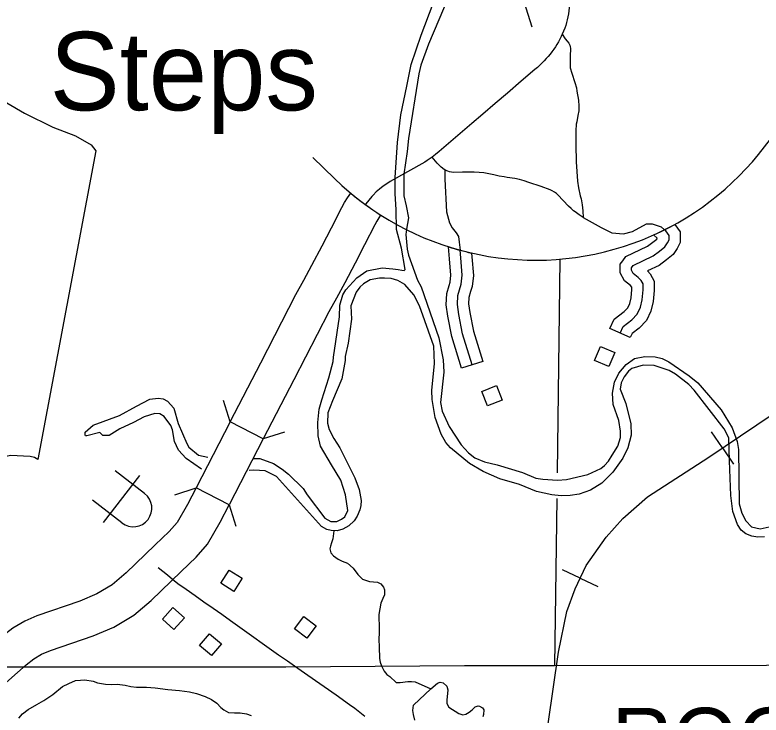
# Model space of a CAD drawing. Extents: x -19 to 366, y -4 to 359.
# Drawn here: x 142.697 to 143.649, y 197.976 to 198.869 of the extents above; entities that cross this region are included whole.
import ezdxf

# ---------------------------------------------------------------- set-up
doc = ezdxf.new("R2010")
doc.units = 0
for name, color, linetype in [('Level 10', 7, 'Continuous'), ('Level 24', 7, 'Continuous'), ('Level 31', 7, 'Continuous'), ('Level 32', 7, 'Continuous'), ('Level 35', 7, 'Continuous'), ('Level 37', 7, 'Continuous'), ('Level 40', 7, 'Continuous'), ('Level 5', 7, 'Continuous'), ('Level 50', 7, 'Continuous'), ('Level 56', 7, 'Continuous'), ('Level 57', 7, 'Continuous'), ('Level 60', 7, 'Continuous'), ('Level 63', 7, 'Continuous'), ('Level 9', 7, 'Continuous')]:
    doc.layers.add(name, color=color, linetype=linetype)

msp = doc.modelspace()

# ---------------------------------------------------------------- linework, layer by layer
at = {"layer": 'Level 10'}
for p, q in [((143.01371, 198.32807), (142.97164, 198.34979)), ((142.97012, 198.24366), (142.92805, 198.26538)), ((142.86331, 198.1804), (142.8633, 198.1804))]:
    msp.add_line(p, q, dxfattribs=at)
for points in [[(143.40417, 198.88423), (143.40409, 198.88139), (143.40383, 198.87758), (143.40345, 198.87378), (143.40292, 198.87), (143.40225, 198.86624), (143.40144, 198.86251), (143.40049, 198.85881), (143.39939, 198.85516), (143.39817, 198.85154), (143.39681, 198.84797), (143.39508, 198.84394)], [(143.39508, 198.84394), (143.39375, 198.84103), (143.39205, 198.83764), (143.39023, 198.83432), (143.38832, 198.83105), (143.38628, 198.82785), (143.38417, 198.82472), (143.38194, 198.82165), (143.37959, 198.81867), (143.37717, 198.81576), (143.37465, 198.81293), (143.37203, 198.81019), (143.36934, 198.80753), (143.36334, 198.8016), (143.36022, 198.79879), (143.34283, 198.78409), (143.32507, 198.76896), (143.30965, 198.75576), (143.29388, 198.74222), (143.27967, 198.73011), (143.23825, 198.69453), (143.23331, 198.69039), (143.22935, 198.68738)], [(143.22935, 198.68738), (143.22288, 198.68282), (143.2196, 198.68074), (143.17569, 198.65616), (143.17116, 198.65329), (143.16652, 198.65004), (143.16206, 198.64654), (143.15779, 198.64281), (143.15371, 198.63886), (143.15211, 198.63707), (143.1482, 198.63243), (143.14455, 198.62761), (143.14395, 198.62673)], [(142.97164, 198.34979), (143.01053, 198.42512), (143.0555, 198.51224), (143.06561, 198.53029), (143.0759, 198.54936), (143.08903, 198.57406), (143.1007, 198.59702), (143.11417, 198.62321), (143.11749, 198.6293), (143.12126, 198.63546), (143.12526, 198.64135)], [(143.16347, 198.61333), (143.16104, 198.60977), (143.15849, 198.6056), (143.15602, 198.60106), (143.14286, 198.57547), (143.13104, 198.55222), (143.11763, 198.52701), (143.1071, 198.50748), (143.0972, 198.48981), (143.0526, 198.4034), (143.01371, 198.32807)], [(142.97164, 198.34979), (142.92805, 198.26538)], [(143.01371, 198.32807), (142.97012, 198.24366)], [(142.92805, 198.26538), (142.91718, 198.24432), (142.9039, 198.22135), (142.89392, 198.20998), (142.87607, 198.19272), (142.86331, 198.1804)], [(142.89619, 198.14633), (142.90897, 198.15867), (142.92822, 198.17729), (142.94256, 198.19362), (142.95873, 198.22159), (142.97012, 198.24366)], [(142.8633, 198.1804), (142.8391, 198.15703), (142.82098, 198.14198), (142.80157, 198.13019), (142.77981, 198.12101), (142.72522, 198.10222), (142.70968, 198.09557), (142.69453, 198.0866), (142.68137, 198.07628), (142.52507, 197.93861), (142.4898, 197.90757), (142.47396, 197.8914), (142.46067, 197.87294), (142.43613, 197.83227), (142.43194, 197.82633)], [(142.47062, 197.79903), (142.47579, 197.80635), (142.50021, 197.84683), (142.51029, 197.86082), (142.5224, 197.87318), (142.55636, 197.90308), (142.71165, 198.03986), (142.72131, 198.04743), (142.73114, 198.05325), (142.74227, 198.05801), (142.79673, 198.07676), (142.82319, 198.08792), (142.84854, 198.10333), (142.87071, 198.12174), (142.89619, 198.14634)]]:
    msp.add_lwpolyline(points, dxfattribs=at)
msp.add_arc((143.36999, 198.93506), 0.3823, 230.19832, 237.30333, dxfattribs=at)
at = {"layer": 'Level 31'}
for p, q in [((143.47228, 198.5552), (143.47228, 198.5552)), ((143.25094, 198.52364), (143.25094, 198.52364)), ((143.48169, 198.45707), (143.45582, 198.46882)), ((143.29358, 198.42654), (143.2664, 198.41831))]:
    msp.add_line(p, q, dxfattribs=at)
for points in [[(143.39508, 198.84394), (143.39857, 198.83816), (143.40122, 198.83503), (143.40322, 198.83253), (143.40457, 198.83), (143.40529, 198.8281), (143.40559, 198.82609), (143.40546, 198.82406), (143.4052, 198.81759), (143.40506, 198.80117), (143.40706, 198.79429), (143.41113, 198.78262), (143.41338, 198.77576), (143.41377, 198.77141), (143.41554, 198.75982), (143.41614, 198.7524), (143.41606, 198.74638), (143.41508, 198.74032), (143.41355, 198.7322), (143.41259, 198.72931), (143.4122, 198.72097), (143.41225, 198.70277), (143.41264, 198.68119), (143.41454, 198.6565), (143.41581, 198.64808), (143.41804, 198.63776), (143.41917, 198.63405), (143.42029, 198.62652), (143.42131, 198.61861), (143.42168, 198.61016)], [(143.42168, 198.61016), (143.41678, 198.61347), (143.41133, 198.61746), (143.40953, 198.61887), (143.40627, 198.62171), (143.4032, 198.62475), (143.38952, 198.6393), (143.38751, 198.641), (143.38497, 198.64276), (143.38229, 198.64426), (143.37946, 198.6455), (143.36796, 198.64977), (143.35236, 198.65504), (143.3465, 198.65695), (143.34063, 198.65856), (143.33467, 198.65988), (143.3248, 198.66137), (143.32113, 198.66191), (143.31439, 198.66315), (143.30771, 198.66467), (143.29737, 198.66685), (143.29511, 198.66717), (143.289, 198.66781), (143.28288, 198.66814), (143.27675, 198.66818), (143.27267, 198.6682), (143.26782, 198.6681), (143.25632, 198.66782), (143.2538, 198.66798), (143.25135, 198.66845), (143.24896, 198.6692), (143.24668, 198.67024), (143.24453, 198.67154), (143.2408, 198.67445), (143.23812, 198.67693), (143.23564, 198.67961), (143.22935, 198.68738)], [(143.24536, 198.67104), (143.24516, 198.65914), (143.24757, 198.61768), (143.25117, 198.60326), (143.25477, 198.59725), (143.25957, 198.59065), (143.26258, 198.58584), (143.26378, 198.57863), (143.26469, 198.56861)], [(143.42168, 198.61016), (143.44472, 198.59767), (143.45845, 198.5908), (143.47295, 198.58928), (143.48477, 198.59233), (143.50232, 198.60225), (143.50957, 198.60225), (143.52101, 198.59844), (143.52538, 198.59461)], [(143.53854, 198.60153), (143.54551, 198.59202), (143.54551, 198.57829), (143.54166, 198.57057), (143.53641, 198.56299), (143.52777, 198.55627), (143.51854, 198.54923), (143.50358, 198.54208)], [(143.46875, 198.46295), (143.47257, 198.47134), (143.48363, 198.47974), (143.4905, 198.48699), (143.49469, 198.49577), (143.49698, 198.50531), (143.49812, 198.51791), (143.49812, 198.52554), (143.49584, 198.52974), (143.49164, 198.53394), (143.48554, 198.5389), (143.48325, 198.5431), (143.48325, 198.54615), (143.48554, 198.5492), (143.51109, 198.56141), (143.5191, 198.56752), (143.52597, 198.57286), (143.5294, 198.57783), (143.53131, 198.58164), (143.53131, 198.58737), (143.52711, 198.59309), (143.52538, 198.59461)], [(143.47228, 198.5552), (143.47626, 198.56051), (143.50365, 198.5736), (143.51044, 198.57877), (143.51553, 198.58274), (143.51623, 198.58375), (143.5114, 198.58797)], [(143.25094, 198.52364), (143.25219, 198.52791), (143.25312, 198.53675), (143.25143, 198.55759), (143.25003, 198.57291)], [(143.27999, 198.42243), (143.26798, 198.46208), (143.26318, 198.48671), (143.26138, 198.49933), (143.26198, 198.51074), (143.26618, 198.52516), (143.26738, 198.53658), (143.26558, 198.5588), (143.26469, 198.56861)], [(143.27928, 198.56496), (143.27973, 198.56002), (143.28165, 198.5364), (143.28017, 198.52241), (143.27822, 198.51569)], [(143.45582, 198.46882), (143.46112, 198.48049), (143.47411, 198.49035), (143.47864, 198.49514), (143.48123, 198.50054), (143.48293, 198.50762), (143.48392, 198.51855), (143.48392, 198.52157), (143.48211, 198.52338), (143.4744, 198.52964), (143.46904, 198.53948), (143.46904, 198.55088), (143.47228, 198.5552)], [(143.50358, 198.54208), (143.50733, 198.53833), (143.51233, 198.52916), (143.51233, 198.51726), (143.51103, 198.503), (143.50815, 198.491), (143.50235, 198.47885), (143.49314, 198.46913), (143.48402, 198.4622), (143.48169, 198.45707)], [(143.2664, 198.41831), (143.25418, 198.45865), (143.24917, 198.48435), (143.24712, 198.49869), (143.24788, 198.51313), (143.25094, 198.52364)], [(143.27822, 198.51569), (143.27607, 198.50835), (143.27563, 198.49996), (143.27719, 198.48907), (143.28178, 198.4655), (143.29358, 198.42654)], [(143.14343, 197.97369), (143.13709, 197.97901), (143.13059, 197.98409), (143.12386, 197.98894), (143.10685, 198.00097), (143.07044, 198.02632), (143.06616, 198.02929), (143.05796, 198.03491), (143.05346, 198.03803), (143.04456, 198.0443), (143.03341, 198.05217), (143.02147, 198.06066), (142.99274, 198.08121), (142.97203, 198.0959), (142.96085, 198.10382), (142.94991, 198.11155), (142.93806, 198.11984), (142.92698, 198.12759), (142.91544, 198.13574), (142.90505, 198.1432), (142.89795, 198.14876), (142.8918, 198.15402), (142.87975, 198.16337)]]:
    msp.add_lwpolyline(points, dxfattribs=at)
for centre, radius, start, end in [((143.36097, 198.92315), 0.36738, 294.17111, 298.90429), ((143.36097, 198.92313), 0.36737, 252.42411, 257.15276)]:
    msp.add_arc(centre, radius, start, end, dxfattribs=at)
at = {"layer": 'Level 32'}
msp.add_lwpolyline([(143.33736, 198.9305), (143.33703, 198.91934), (143.33823, 198.91033), (143.35624, 198.85325)], dxfattribs=at)
at = {"layer": 'Level 35'}
for points in [[(142.80029, 198.69527), (142.72628, 198.30157)], [(143.10377, 198.21087), (143.10243, 198.20043), (143.1009, 198.19531), (143.09938, 198.19133), (143.09862, 198.18772), (143.09994, 198.18241), (143.10335, 198.17861), (143.10921, 198.17443), (143.11451, 198.17215), (143.12114, 198.1693), (143.12852, 198.16322), (143.13457, 198.15487), (143.14044, 198.14917), (143.14915, 198.14613), (143.15937, 198.14536), (143.16373, 198.14327), (143.16713, 198.1389), (143.16827, 198.13549), (143.16826, 198.12885), (143.16617, 198.12448), (143.1637, 198.11842), (143.16122, 198.10381), (143.16138, 198.08522), (143.16138, 198.08085), (143.16118, 198.07212), (143.16136, 198.06264), (143.16191, 198.04784), (143.16304, 198.04328), (143.16455, 198.03854), (143.16795, 198.03152), (143.17135, 198.02753), (143.17533, 198.02506), (143.18308, 198.01746), (143.1882, 198.01708), (143.19805, 198.0184), (143.20297, 198.01858), (143.20733, 198.01801), (143.2274, 198.00908)], [(143.2274, 198.00908), (143.23593, 198.01628), (143.23953, 198.0176), (143.24313, 198.01684), (143.24805, 198.01266), (143.24899, 198.00773), (143.24803, 197.99483), (143.24765, 197.99274), (143.24783, 197.99028), (143.25029, 197.98572), (143.26316, 197.97755), (143.26808, 197.97622), (143.27187, 197.97678), (143.27642, 197.97925), (143.28002, 197.98228), (143.28401, 197.98626), (143.28647, 197.9872), (143.2878, 197.98758), (143.2895, 197.9872), (143.29348, 197.98511), (143.29499, 197.98245), (143.29479, 197.97638), (143.29365, 197.97335)], [(143.20708, 197.96925), (143.20538, 197.97627), (143.20444, 197.98159), (143.2054, 197.98842), (143.2274, 198.00908)]]:
    msp.add_lwpolyline(points, dxfattribs=at)
at = {"layer": 'Level 37'}
for points in [[(142.97164, 198.34979), (142.963, 198.37685)], [(143.04077, 198.3367), (143.01371, 198.32807)], [(142.90099, 198.25674), (142.92805, 198.26538)], [(142.97012, 198.24366), (142.97876, 198.21659)]]:
    msp.add_lwpolyline(points, dxfattribs=at)
at = {"layer": 'Level 40'}
for p, q in [((143.59933, 198.31636), (143.58536, 198.33709)), ((143.59933, 198.31636), (143.6133, 198.29563)), ((143.41788, 198.1503), (143.3953, 198.16105)), ((143.41788, 198.1503), (143.44045, 198.13956))]:
    msp.add_line(p, q, dxfattribs=at)
for points in [[(143.45095, 198.20245), (143.47209, 198.22643), (143.5038, 198.25392), (143.58202, 198.30469), (143.68349, 198.37308), (143.72084, 198.40128), (143.7455, 198.42455), (143.76734, 198.45063), (143.78778, 198.48377), (143.80399, 198.52184), (143.81597, 198.57049), (143.81949, 198.60434), (143.81597, 198.64311), (143.80892, 198.67978), (143.79342, 198.71997), (143.6849, 198.93219), (143.49394, 199.29811), (143.30931, 199.65769), (143.18177, 199.90658), (143.1564, 199.93901), (143.12821, 199.9651), (143.10496, 199.98343)], [(143.37062, 197.92043), (143.39035, 198.0558), (143.40092, 198.10798), (143.41149, 198.13688), (143.42558, 198.1665), (143.45095, 198.20245), (143.47209, 198.22643), (143.5038, 198.25392), (143.58202, 198.30469), (143.68349, 198.37308)], [(143.37062, 197.92043), (143.39035, 198.0558), (143.40092, 198.10798), (143.41149, 198.13688), (143.42558, 198.1665), (143.45095, 198.20245)]]:
    msp.add_lwpolyline(points, dxfattribs=at)
at = {"layer": 'Level 5'}
for points in [[(143.39211, 198.55709), (143.38851, 198.28475)], [(143.38807, 198.25188), (143.38526, 198.03905)]]:
    msp.add_lwpolyline(points, dxfattribs=at)
at = {"layer": 'Level 50'}
msp.add_lwpolyline([(142.70203, 197.97177), (142.70673, 197.9773), (142.7139, 197.98304), (142.72522, 197.989), (142.73389, 197.99419), (142.74559, 198.00205), (142.75765, 198.01219), (142.76576, 198.01604), (142.77425, 198.0197), (142.78068, 198.02031), (142.78616, 198.02054), (142.79695, 198.01909), (142.80244, 198.01704), (142.81266, 198.01502), (142.82004, 198.01469), (142.8276, 198.01512), (142.83782, 198.01386), (142.84501, 198.0122), (142.8522, 198.01111), (142.85939, 198.01116), (142.86506, 198.01139), (142.87584, 198.01051), (142.8923, 198.00834), (142.90687, 198.00692), (142.91954, 198.0053), (142.92844, 198.00327), (142.9398, 197.99955), (142.94795, 197.99562), (142.9544, 197.99111), (142.95952, 197.98545), (142.96332, 197.98225), (142.96939, 197.97887), (142.97695, 197.97855), (142.98433, 197.97841), (142.99227, 197.97713), (142.99814, 197.97527)], dxfattribs=at)
at = {"layer": 'Level 56'}
for points in [[(143.46192, 198.43822), (143.45422, 198.42008), (143.43602, 198.4278), (143.44372, 198.44595)], [(143.311, 198.39582), (143.31825, 198.37749), (143.29986, 198.37022), (143.29261, 198.38855)], [(142.98693, 198.15013), (142.9764, 198.13346), (142.95968, 198.14402), (142.97021, 198.16069)], [(142.91315, 198.09959), (142.89993, 198.08497), (142.88526, 198.09822), (142.89848, 198.11285)], [(143.08113, 198.08949), (143.06927, 198.07374), (143.05347, 198.08563), (143.06533, 198.10138)], [(142.94529, 198.07938), (142.96037, 198.06667), (142.94763, 198.05155), (142.93255, 198.06426)]]:
    msp.add_lwpolyline(points, close=True, dxfattribs=at)
at = {"layer": 'Level 57'}
for p, q in [((142.86255, 198.2583), (142.82507, 198.28725)), ((142.80993, 198.22117), (142.85624, 198.28112)), ((142.8336, 198.22083), (142.79613, 198.24977))]:
    msp.add_line(p, q, dxfattribs=at)
msp.add_arc((142.84807, 198.23957), 0.02367, 232.31688, 52.31688, dxfattribs=at)
at = {"layer": 'Level 60'}
for points in [[(146.77834, 1.69699), (146.57878, 10.31313), (146.37852, 18.92942), (146.17757, 27.54584), (145.97591, 36.16241), (145.77356, 44.77911), (145.57052, 53.39596), (145.36679, 62.01295), (145.16236, 70.63008), (144.95724, 79.24735), (144.75142, 87.86477), (144.54492, 96.48232), (144.33773, 105.10002), (144.12986, 113.71787), (143.92129, 122.33585), (143.71204, 130.95398), (143.5021, 139.57225), (143.29148, 148.19067), (143.08018, 156.80923), (142.8682, 165.42794), (142.65553, 174.04679), (142.44218, 182.66579), (142.22816, 191.28493), (142.01345, 199.90421), (141.79807, 208.52365), (141.58202, 217.14322), (141.36528, 225.76295), (141.14788, 234.38282), (140.9298, 243.00284), (140.71105, 251.623), (140.49162, 260.24332), (140.27153, 268.86377), (140.05077, 277.48438), (139.82934, 286.10514), (139.60724, 294.72604), (139.38447, 303.34709), (139.16105, 311.96829), (138.93695, 320.58964), (138.7122, 329.21114), (138.48678, 337.83278), (138.2607, 346.45458)], [(0, 198.13258), (7.10141, 198.13701), (14.2028, 198.15029), (21.30418, 198.17244), (28.40552, 198.20345), (35.50682, 198.24331), (42.60806, 198.29203), (49.70923, 198.34961), (56.81033, 198.41605), (63.91134, 198.49135), (71.01225, 198.5755), (78.11305, 198.66852), (85.21373, 198.77039), (92.31428, 198.88112), (99.41468, 199.0007), (106.51492, 199.12915), (113.61501, 199.26645), (120.71491, 199.4126), (127.81463, 199.56762), (134.91415, 199.73149), (142.01345, 199.90421), (149.11254, 200.0858), (156.2114, 200.27623), (163.31001, 200.47553), (170.40837, 200.68367), (177.50646, 200.90068), (184.60427, 201.12653), (191.7018, 201.36125), (198.79903, 201.60481), (205.89596, 201.85723), (212.99256, 202.1185), (220.08883, 202.38862), (227.18475, 202.6676), (234.28033, 202.95542), (241.37554, 203.2521), (248.47037, 203.55763), (255.56482, 203.87201), (262.65887, 204.19524), (269.75251, 204.52732), (276.84573, 204.86824), (283.93852, 205.21802), (291.03086, 205.57664), (298.12276, 205.94411), (305.21419, 206.32042), (312.30515, 206.70559), (319.39562, 207.09959), (326.48559, 207.50244), (333.57505, 207.91414), (340.664, 208.33468)], [(0, 189.51617), (7.11214, 189.52059), (14.22427, 189.53386), (21.33637, 189.55597), (28.44845, 189.58693), (35.56048, 189.62672), (42.67245, 189.67537), (49.78436, 189.73285), (56.89619, 189.79918), (64.00793, 189.87436), (71.11958, 189.95838), (78.23111, 190.05124), (85.34253, 190.15294), (92.45381, 190.26349), (99.56495, 190.38288), (106.67593, 190.51112), (113.78675, 190.6482), (120.89739, 190.79412), (128.00785, 190.94888), (135.11811, 191.11248), (142.22816, 191.28493), (149.33799, 191.46621), (156.44759, 191.65634), (163.55694, 191.85531), (170.66605, 192.06312), (177.77489, 192.27977), (184.88345, 192.50526), (191.99173, 192.73959), (199.09971, 192.98276), (206.20739, 193.23477), (213.31474, 193.49561), (220.42177, 193.7653), (227.52845, 194.04382), (234.63479, 194.33118), (241.74076, 194.62738), (248.84635, 194.93241), (255.95157, 195.24628), (263.05638, 195.56898), (270.16079, 195.90052), (277.26478, 196.24089), (284.36834, 196.5901), (291.47147, 196.94814), (298.57414, 197.31501), (305.67635, 197.69072), (312.77809, 198.07525), (319.87934, 198.46862), (326.9801, 198.87082), (334.08035, 199.28185), (341.18009, 199.7017)]]:
    msp.add_spline(points, degree=3, dxfattribs=at)
at = {"layer": 'Level 63'}
for points in [[(143.07701, 198.68687), (143.10468, 198.65993)], [(140.83205, 198.03809), (141.26817, 198.0367), (141.39108, 198.03674), (142.26862, 198.03703), (142.39046, 198.03707), (143.04238, 198.03729), (143.27017, 198.03888), (143.38526, 198.03905), (145.27639, 198.04185)]]:
    msp.add_lwpolyline(points, dxfattribs=at)
msp.add_arc((143.36097, 198.92314), 0.36738, 225.76353, 349.85724, dxfattribs=at)
at = {"layer": 'Level 9'}
for points in [[(142.20175, 198.96157), (142.23718, 198.9499), (142.25951, 198.93938), (142.29895, 198.91257), (142.31347, 198.90479), (142.32834, 198.89872), (142.34906, 198.89539), (142.37079, 198.88714), (142.39021, 198.88133), (142.41131, 198.87743), (142.42534, 198.87743), (142.44187, 198.87461), (142.47175, 198.86685), (142.52482, 198.84117), (142.56668, 198.81743), (142.6413, 198.78293), (142.70936, 198.74341), (142.74545, 198.72547), (142.77423, 198.71447), (142.79449, 198.70278), (142.80029, 198.69527)], [(143.25095, 198.89391), (143.22454, 198.8313), (143.21469, 198.8046), (143.212, 198.79356)], [(143.185, 198.70589), (143.18905, 198.74124), (143.19706, 198.7776), (143.20217, 198.80519), (143.21528, 198.84295), (143.23044, 198.8832)], [(143.212, 198.79356), (143.19896, 198.7112), (143.1973, 198.69447), (143.19316, 198.66557), (143.19317, 198.63804), (143.19583, 198.62498), (143.19908, 198.60965), (143.19625, 198.59538), (143.19577, 198.58873), (143.19718, 198.56977), (143.1988, 198.56239), (143.21045, 198.53027), (143.21512, 198.52199), (143.23747, 198.45661), (143.24337, 198.4286), (143.24397, 198.41304), (143.23979, 198.37427), (143.24184, 198.36328), (143.25065, 198.34385), (143.26596, 198.32033), (143.27539, 198.3102), (143.28364, 198.30386), (143.29603, 198.29871), (143.31183, 198.29475), (143.3442, 198.28493), (143.36117, 198.27794), (143.3701, 198.27654), (143.38907, 198.27546), (143.40025, 198.27618), (143.42784, 198.28262), (143.44404, 198.29005), (143.44891, 198.29391), (143.45395, 198.29967), (143.45877, 198.30714), (143.466, 198.31881), (143.46944, 198.32987), (143.46933, 198.33784), (143.46705, 198.35147), (143.45975, 198.37169), (143.45897, 198.3861), (143.46161, 198.40037)], [(143.17896, 198.54479), (143.18579, 198.54411), (143.19055, 198.54311), (143.19359, 198.54277), (143.19452, 198.54392), (143.18996, 198.57119), (143.18355, 198.59483), (143.18338, 198.62064), (143.18195, 198.64055), (143.18203, 198.66143), (143.185, 198.70589)], [(143.10328, 198.43211), (143.11093, 198.48343), (143.11147, 198.49862), (143.11508, 198.51157), (143.11897, 198.51808), (143.13316, 198.53345), (143.14573, 198.54235), (143.16559, 198.54603), (143.17896, 198.54479)], [(143.16845, 198.533), (143.16179, 198.53307), (143.15007, 198.53064), (143.14161, 198.52578), (143.13693, 198.52155), (143.13228, 198.51522), (143.12533, 198.49748), (143.12614, 198.48078), (143.12189, 198.44988), (143.11842, 198.43291)], [(143.60747, 198.32924), (143.60162, 198.34055), (143.56338, 198.38996), (143.55626, 198.39745), (143.53939, 198.41033), (143.53136, 198.41534), (143.51212, 198.42173), (143.49828, 198.42174), (143.48355, 198.41756), (143.47961, 198.41447), (143.47403, 198.40718), (143.46997, 198.39953), (143.46895, 198.39117), (143.47622, 198.37304), (143.48266, 198.34713), (143.48305, 198.33271), (143.47855, 198.31632), (143.4721, 198.30333), (143.45965, 198.28532), (143.44544, 198.27128), (143.43097, 198.26235), (143.41663, 198.25742), (143.40528, 198.25575), (143.39372, 198.25541), (143.38157, 198.25638), (143.36217, 198.26087), (143.34062, 198.26988), (143.3153, 198.27695), (143.29413, 198.28635), (143.27672, 198.29675), (143.25255, 198.31654), (143.24677, 198.32349), (143.24055, 198.33404), (143.23304, 198.35519), (143.2293, 198.3783), (143.22857, 198.38968), (143.23225, 198.42389), (143.23136, 198.44628), (143.21281, 198.49747), (143.20579, 198.51161), (143.19441, 198.52475), (143.18518, 198.53003), (143.17692, 198.5325), (143.16845, 198.533)], [(143.00182, 198.30312), (143.00932, 198.30287), (143.02704, 198.29646), (143.03795, 198.28939), (143.046, 198.28286), (143.06447, 198.2645), (143.06969, 198.25679), (143.09231, 198.22672), (143.09976, 198.22246), (143.10753, 198.22256), (143.11375, 198.22549), (143.11787, 198.22858), (143.12155, 198.23679), (143.1188, 198.25649), (143.11266, 198.2752), (143.10081, 198.29498), (143.08663, 198.3187), (143.08398, 198.33195), (143.08317, 198.34865), (143.0852, 198.36595), (143.08825, 198.37794), (143.09733, 198.40578), (143.10291, 198.42673), (143.10328, 198.43211)], [(143.11842, 198.43291), (143.11826, 198.42769), (143.11385, 198.40448), (143.10211, 198.37642), (143.09626, 198.36135), (143.09589, 198.34787)], [(143.46161, 198.40037), (143.46714, 198.41164), (143.47665, 198.42278), (143.48734, 198.43051), (143.50039, 198.43315), (143.51348, 198.43276), (143.52223, 198.43041), (143.53101, 198.42616), (143.55705, 198.40828), (143.56798, 198.39951), (143.59786, 198.36517), (143.61165, 198.3422), (143.61797, 198.32444), (143.61982, 198.31422), (143.62081, 198.24495), (143.62401, 198.23303), (143.62927, 198.22323), (143.63639, 198.21593), (143.64723, 198.21341), (143.65876, 198.21585)], [(142.93518, 198.28918), (142.91566, 198.30276), (142.90584, 198.31364), (142.90075, 198.32477), (142.89789, 198.33935), (142.89591, 198.34502), (142.88722, 198.35629), (142.88186, 198.35982), (142.87541, 198.36031), (142.86181, 198.35614), (142.84846, 198.34875), (142.83075, 198.34092), (142.81741, 198.3322), (142.80907, 198.33228), (142.80541, 198.33603), (142.78879, 198.33182), (142.78727, 198.33199), (142.78649, 198.33331), (142.78664, 198.33654), (142.79694, 198.34522), (142.83032, 198.35762), (142.85195, 198.36968), (142.86927, 198.37845), (142.87968, 198.37973), (142.88614, 198.37886), (142.89187, 198.3759), (142.89957, 198.36727), (142.90516, 198.34761), (142.91614, 198.32213), (142.91905, 198.31742), (142.93115, 198.30714)], [(143.09589, 198.34787), (143.09789, 198.34011), (143.10394, 198.32823), (143.11131, 198.31637), (143.13063, 198.2781), (143.13615, 198.26318), (143.13843, 198.24954), (143.13833, 198.24309), (143.13708, 198.23757), (143.13341, 198.22936), (143.12951, 198.22323), (143.12278, 198.21707), (143.11544, 198.21298), (143.10808, 198.21061), (143.1003, 198.21107), (143.09478, 198.21252), (143.08809, 198.21623), (143.06132, 198.24605), (143.0305, 198.28), (143.01618, 198.28702), (143.00156, 198.28815), (142.99597, 198.28741)], [(143.65288, 198.20305), (143.64435, 198.20275), (143.63656, 198.20378), (143.62932, 198.20672), (143.62337, 198.21139), (143.61853, 198.21854), (143.61242, 198.23516), (143.60985, 198.25562), (143.60846, 198.29983), (143.60747, 198.32924)], [(142.72628, 198.30157), (142.72188, 198.30436), (142.71636, 198.30562), (142.69151, 198.30661), (142.67034, 198.30216), (142.6611, 198.29862), (142.6438, 198.28852), (142.62467, 198.27403), (142.61739, 198.26634), (142.59918, 198.24009), (142.59376, 198.23471), (142.59, 198.23295), (142.58524, 198.23402), (142.57894, 198.23736), (142.57376, 198.24165)], [(142.93115, 198.30714), (142.94327, 198.30458)]]:
    msp.add_lwpolyline(points, dxfattribs=at)

# ---------------------------------------------------------------- texts
at = {"layer": 'Level 24'}
msp.add_text('Steps', height=0.1, dxfattribs=at).set_placement((142.74148, 198.74695))
at = {"layer": 'Level 63'}
msp.add_text('ROCK', height=0.08, rotation=0.10438, dxfattribs=at).set_placement((143.45844, 197.90478))

doc.saveas('drawing.dxf')
